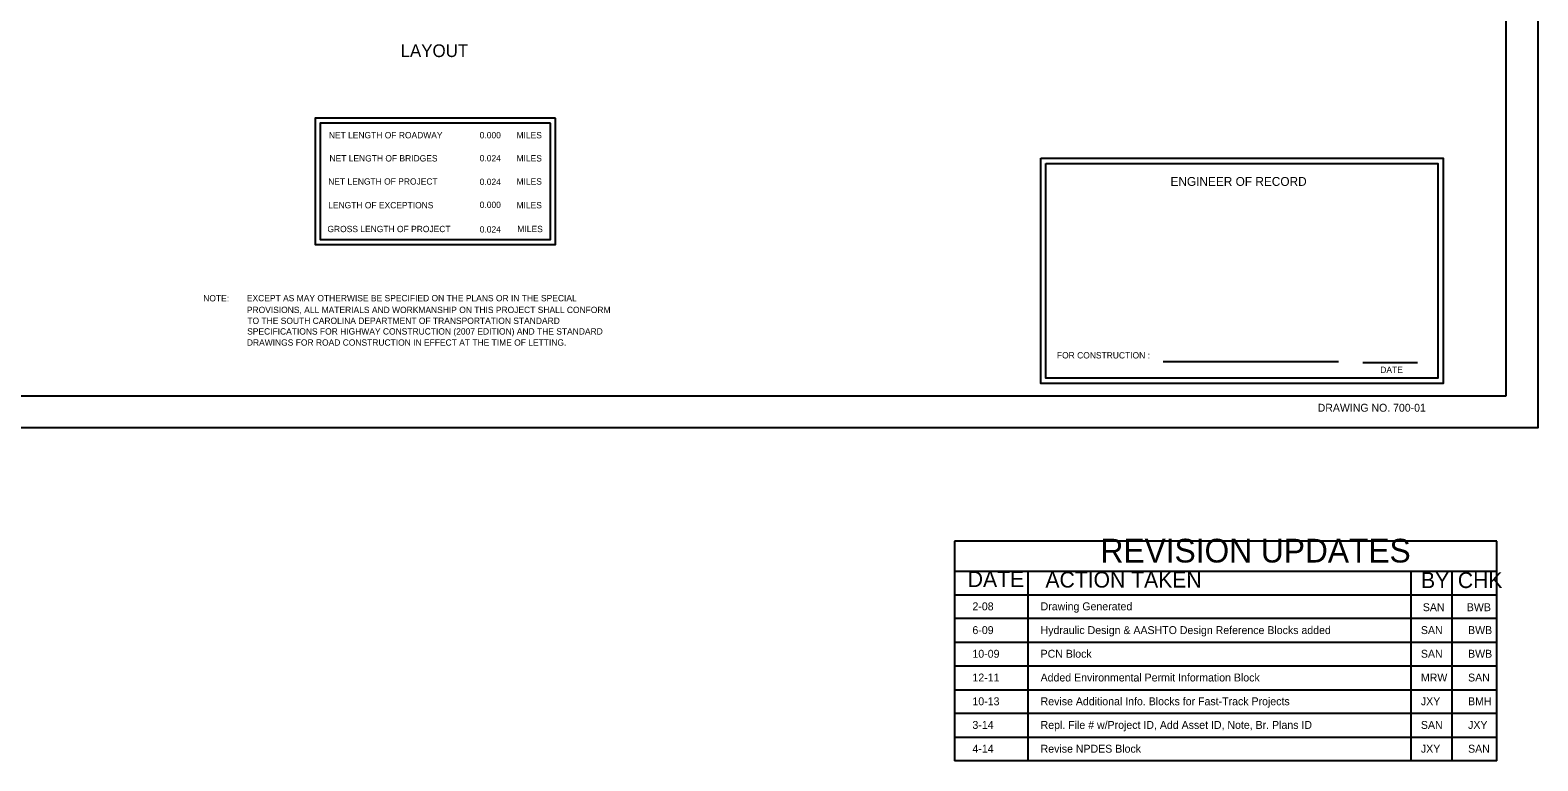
# Model space of a CAD drawing. Extents: x 741 to 2541, y 338 to 1701.
# Drawn here: x 1349 to 2541, y 338 to 916 of the extents above; entities that cross this region are included whole.
import ezdxf

# ---------------------------------------------------------------- set-up
doc = ezdxf.new("R2010")
doc.units = 0
for name, color, linetype in [('BR_BORDER LINES', 7, 'Continuous'), ('BR_TEXT', 7, 'Continuous'), ('Default', 7, 'Continuous'), ('RD_SHT_IplotShp', 7, 'Continuous')]:
    doc.layers.add(name, color=color, linetype=linetype)

msp = doc.modelspace()

# ---------------------------------------------------------------- linework, layer by layer
at = {"layer": 'BR_BORDER LINES'}
for p, q in [((2515.7, 626.3), (2515.7, 1676.3)), ((840.7, 626.3), (2515.7, 626.3)), ((740.7, 601.3), (2540.7, 601.3)), ((2508.2, 511.4), (2079.3, 511.4)), ((2079.3, 511.4), (2079.3, 337.7)), ((2508.2, 337.7), (2508.2, 511.4)), ((2079.3, 487.7), (2508.2, 487.7)), ((2137.5, 487.7), (2137.5, 337.7)), ((2440.4, 337.7), (2440.4, 487.7)), ((2472.7, 487.7), (2472.7, 337.7)), ((2079.3, 469), (2508.2, 469)), ((2508.2, 450.2), (2079.3, 450.2)), ((2079.3, 431.5), (2508.2, 431.5)), ((2508.2, 412.7), (2079.3, 412.7)), ((2079.3, 394), (2508.2, 394)), ((2508.2, 375.2), (2079.3, 375.2)), ((2079.3, 356.5), (2508.2, 356.5)), ((2508.2, 337.7), (2079.3, 337.7))]:
    msp.add_line(p, q, dxfattribs=at)
at = {"layer": 'Default'}
for p, q in [((2244.4, 653.5), (2383, 653.5)), ((2402.2, 652.9), (2445.6, 652.9))]:
    msp.add_line(p, q, dxfattribs=at)
for points in [[(1763.9, 846), (1573.9, 846), (1573.9, 746), (1763.9, 746)], [(1759.9, 842), (1577.9, 842), (1577.9, 750), (1759.9, 750)], [(2147.7, 814.3), (2465.7, 814.3), (2465.7, 636.3), (2147.7, 636.3)], [(2151.7, 810.3), (2461.7, 810.3), (2461.7, 640.3), (2151.7, 640.3)]]:
    msp.add_lwpolyline(points, close=True, dxfattribs=at)
at = {"layer": 'RD_SHT_IplotShp'}
msp.add_lwpolyline([(740.7, 1701.2), (2540.7, 1701.2), (2540.7, 601.2), (740.7, 601.2)], close=True, dxfattribs=at)

# ---------------------------------------------------------------- texts
at = {"layer": 'BR_TEXT'}
msp.add_text('DRAWING NO. 700-01', height=6.219, rotation=360, dxfattribs=at).set_placement((2366.6, 613.9))
for s, height, p in [('REVISION UPDATES', 18.75, (2194.9, 494.6)), ('DATE', 12.5, (2089.9, 475.2)), ('ACTION TAKEN', 12.5, (2151.3, 474.8)), ('BY', 12.5, (2448.3, 474.4)), ('CHK', 12.5, (2477.4, 474.4)), ('2-08', 6.25, (2093.6, 456.8)), ('Drawing Generated', 6.25, (2147.5, 456.8)), ('SAN', 6.25, (2449.7, 456.1)), ('BWB', 6.25, (2484.5, 456.1)), ('6-09', 6.25, (2093.6, 438)), ('Hydraulic Design & AASHTO Design Reference Blocks added', 6.25, (2147.5, 438)), ('SAN', 6.25, (2448.2, 438)), ('BWB', 6.25, (2485.5, 438)), ('10-09', 6.25, (2093.6, 419.3)), ('PCN Block', 6.25, (2147.5, 419.3)), ('SAN', 6.25, (2448.2, 419.3)), ('BWB', 6.25, (2485.5, 419.3)), ('12-11', 6.25, (2093.6, 400.5)), ('Added Environmental Permit Information Block', 6.25, (2147.5, 400.5)), ('MRW', 6.25, (2448.2, 400.5)), ('SAN', 6.25, (2485.5, 400.5)), ('10-13', 6.25, (2093.6, 381.7)), ('Revise Additional Info. Blocks for Fast-Track Projects', 6.25, (2147.5, 381.7)), ('JXY', 6.25, (2448.2, 381.7)), ('BMH', 6.25, (2485.5, 381.7)), ('Repl. File # w/Project ID, Add Asset ID, Note, Br. Plans ID', 6.25, (2147.5, 363)), ('3-14', 6.25, (2093.6, 363)), ('SAN', 6.25, (2448.2, 363)), ('JXY', 6.25, (2485.5, 363)), ('4-14 ', 6.25, (2093.6, 344.2)), ('Revise NPDES Block                                       ', 6.25, (2147.5, 344.2)), ('JXY', 6.25, (2448.2, 344.2)), ('SAN', 6.25, (2485.5, 344.2))]:
    msp.add_text(s, height=height, dxfattribs=at).set_placement(p)
at = {"layer": 'Default'}
for s, height, p in [('LAYOUT', 10, (1641.4, 894.4)), ('NET LENGTH OF ROADWAY', 5, (1584.7, 830.1)), ('0.000', 5, (1704, 830.1)), ('MILES', 5, (1733.1, 830.1)), ('NET LENGTH OF BRIDGES', 5, (1585.2, 811.8)), ('0.024', 5, (1704, 811.9)), ('MILES', 5, (1733.1, 811.8)), ('ENGINEER OF RECORD', 7, (2250.2, 792.5)), ('NET LENGTH OF PROJECT', 5, (1584.2, 793.5)), ('0.024', 5, (1704, 793.2)), ('MILES', 5, (1733.1, 793.5)), ('LENGTH OF EXCEPTIONS', 5, (1584.2, 774.7)), ('0.000', 5, (1704, 775)), ('MILES', 5, (1733.1, 774.7)), ('GROSS LENGTH OF PROJECT', 5, (1583.6, 755.9)), ('0.024', 5, (1704, 755.6)), ('MILES', 5, (1733.8, 755.9)), ('NOTE:', 5, (1485.4, 701.1)), ('EXCEPT AS MAY OTHERWISE BE SPECIFIED ON THE PLANS OR IN THE SPECIAL ', 5, (1519.9, 701.2)), ('PROVISIONS, ALL MATERIALS AND WORKMANSHIP ON THIS PROJECT SHALL CONFORM ', 5, (1519.9, 691.9)), ('TO THE SOUTH CAROLINA DEPARTMENT OF TRANSPORTATION STANDARD ', 5, (1520.3, 683.3)), ('SPECIFICATIONS FOR HIGHWAY CONSTRUCTION (2007 EDITION) AND THE STANDARD', 5, (1520.1, 674.9)), ('DRAWINGS FOR ROAD CONSTRUCTION IN EFFECT AT THE TIME OF LETTING.', 5, (1519.9, 666.1)), ('FOR CONSTRUCTION :', 5, (2160.4, 656)), ('DATE', 5, (2416.1, 644.5))]:
    msp.add_text(s, height=height, dxfattribs=at).set_placement(p)

doc.saveas('drawing.dxf')
